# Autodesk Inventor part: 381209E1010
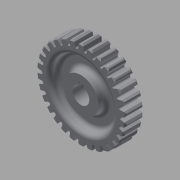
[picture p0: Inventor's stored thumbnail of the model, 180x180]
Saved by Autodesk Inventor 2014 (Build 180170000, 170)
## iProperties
Created: 2018-12
Part Number: 381209E1010
Material: Generic
Document SubType Name: Modeling
Designer: kh
Density: 1 g/cm^3
Appearance: Default
Author: kh
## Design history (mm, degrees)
sketch "Sketch1"
  geometry: L1 (-32, 0)-(32, 0); L2 (0, 0.813)-(0, 38.391); C1 r 30 at (0, 0); A1 r 32 centre (0, 0) between (-32, 0) and (32, 0); A2 r 27.5 centre (0, 0) between (-2, 27.427) and (2, 27.427); A3 r 32 centre (0, 0) between (1.5, 31.965) and (-1.5, 31.965); A4 r 37.907 centre (-35.861, 25.552) between (2, 27.427) and (1.5, 31.965); A5 r 37.907 centre (35.861, 25.552) between (-1.5, 31.965) and (-2, 27.427); 5 further points
  constraints: 12 point on circle, 6 centre point, 4 coincident, 4 end point, 3 symmetric about line, 2 midpoint, 1 horizontal, 1 perpendicular, 1 point on line, 4 other
  dimensions: "d5" = 2 radial gap between concentric circles of A1 C1; "d6" = 60 diameter of C1 (= 30 x d5); "d7" = 2.5 dimension on C1 (= 1.25 x d5); "d13" = 37.90697 radius of A4; "d14" = 32 radius of A3; "d15" = 3 distance of A3.start A3.end; "d16" = 4 distance of A2.end A2.start
extrude "Extrusion1" new body sketch "Sketch1" distance "d17" = 13; taper "d18" = 0 deg
chamfer "Chamfer1" distance "d22" = 1; stored, may be unused: second distance "d23" = 2, angle "d24" = 45 deg
fillet "Fillet1" dims "d25" = 1
chamfer "Chamfer2" distance "d29" = 1; stored, may be unused: second distance "d30" = 2, angle "d31" = 45 deg
sketch "Sketch2"
  geometry: L1 (28.275, 13)-(27.353, 13) reference; L2 (28.275, 13)-(30.956, 13) reference; L3 (30.956, 13)-(30.956, 13) reference; L4 (30.956, 13)-(28.275, 13) reference; L5 (27.353, 13)-(28.275, 13) reference; L6 (27.353, 13)-(27.346, 13) reference; L7 (28.063, 13)-(27.346, 13) reference; L8 (28.063, 13)-(30.624, 13) reference; L9 (29.934, 13)-(30.624, 13) reference; L10 (29.934, 13)-(27.252, 13) reference; L11 (26.164, 13)-(27.252, 13) reference; L12 (26.164, 13)-(26.144, 13) reference; L13 (26.623, 13)-(26.144, 13) reference; L14 (26.623, 13)-(28.954, 13) reference; L15 (27.604, 13)-(28.954, 13) reference; L16 (27.604, 13)-(25.038, 13) reference; L17 (23.832, 13)-(25.038, 13) reference; L18 (23.832, 13)-(23.8, 13) reference; L19 (24.021, 13)-(23.8, 13) reference; L20 (24.021, 13)-(26.019, 13) reference; L21 (24.068, 13)-(26.019, 13) reference; L22 (24.068, 13)-(21.73, 13) reference; L23 (20.458, 13)-(21.73, 13) reference; L24 (20.458, 13)-(20.415, 13) reference; L25 (20.368, 13)-(20.415, 13) reference; L26 (20.368, 13)-(21.946, 13) reference; L27 (19.48, 13)-(21.946, 13) reference; L28 (19.48, 13)-(17.472, 13) reference; L29 (16.19, 13)-(17.472, 13) reference; L30 (16.19, 13)-(16.138, 13) reference; L31 (15.825, 13)-(16.138, 13) reference; L32 (15.825, 13)-(16.915, 13) reference; L33 (14.041, 13)-(16.915, 13) reference; L34 (14.041, 13)-(12.45, 13) reference; L35 (11.215, 13)-(12.45, 13) reference; L36 (11.215, 13)-(11.156, 13) reference; L37 (10.591, 13)-(11.156, 13) reference; L38 (10.591, 13)-(11.144, 13) reference; L39 (7.988, 13)-(11.144, 13) reference; L40 (7.988, 13)-(6.885, 13) reference; L41 (5.749, 13)-(6.885, 13) reference; L42 (5.749, 13)-(5.686, 13) reference; L43 (4.893, 13)-(5.686, 13) reference; L44 (4.893, 13)-(4.886, 13) reference; L45 (1.586, 13)-(4.886, 13) reference; L46 (1.586, 13)-(1.018, 13) reference; L47 (0.032, 13)-(1.018, 13) reference; L48 (0.032, 13)-(-0.032, 13) reference; L49 (-1.018, 13)-(-0.032, 13) reference; L50 (-1.018, 13)-(-1.586, 13) reference; L51 (-4.886, 13)-(-1.586, 13) reference; L52 (-4.886, 13)-(-4.893, 13) reference; L53 (-5.686, 13)-(-4.893, 13) reference; L54 (-5.686, 13)-(-5.749, 13) reference; L55 (-6.885, 13)-(-5.749, 13) reference; L56 (-6.885, 13)-(-7.988, 13) reference; L57 (-11.144, 13)-(-7.988, 13) reference; L58 (-11.144, 13)-(-10.591, 13) reference; L59 (-11.156, 13)-(-10.591, 13) reference; L60 (-11.156, 13)-(-11.215, 13) reference; L61 (-12.45, 13)-(-11.215, 13) reference; L62 (-12.45, 13)-(-14.041, 13) reference; L63 (-16.915, 13)-(-14.041, 13) reference; L64 (-16.915, 13)-(-15.825, 13) reference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; 1 further point
  constraints: 10 end point, 3 perpendicular, 1 collinear, 1 horizontal, 1 parallel
  dimensions: "d35" = 7 distance between parallel lines of L337 L184; "d36" = 45 diameter of L366 L365; "d37" = 25 diameter of L183 L365
revolve "Revolution1" sketch "Sketch2" stored, may be unused: angle "d38" = 90 deg
fillet "Fillet2" dims "d39" = 3
sketch "Sketch3" dims "d40" = 12
  geometry: L1 (-2, 7.768)-(2, 7.768); L2 (2, 7.768)-(2, -0.032); L3 (2, -0.032)-(-2, -0.032); L4 (-2, -0.032)-(-2, 7.768); L5 (0, -6.032)-(0, 7.768); 2 further points
  constraints: 10 end point, 2 midpoint, 2 parallel, 1 coincident, 1 horizontal, 1 perpendicular, 1 point on line, 1 vertical, 1 vertical alignment, 2 other
  dimensions: "d41" = 13.8 dimension on L1; "d42" = 4 distance of L1.start L1.end
extrude "Extrusion2" cut sketch "Sketch3" stored distance "d43" = 13; taper "d44" = 0 deg
body "Solid1"
pattern_circular "Circular Pattern3" dims "d33" = 360 deg
node "Projected Loop1"
node "Projected Loop2"
other parameters: "d12" = 3
